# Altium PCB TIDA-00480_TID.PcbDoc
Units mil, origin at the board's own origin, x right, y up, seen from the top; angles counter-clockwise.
Board outline 5000 x 2500 mil, 2 copper layers (Layer 1 - Top Layer, Layer 2 - Bottom Layer), stack 93 mil thick; 63 components, 60 nets, 208 pads, 58 vias.
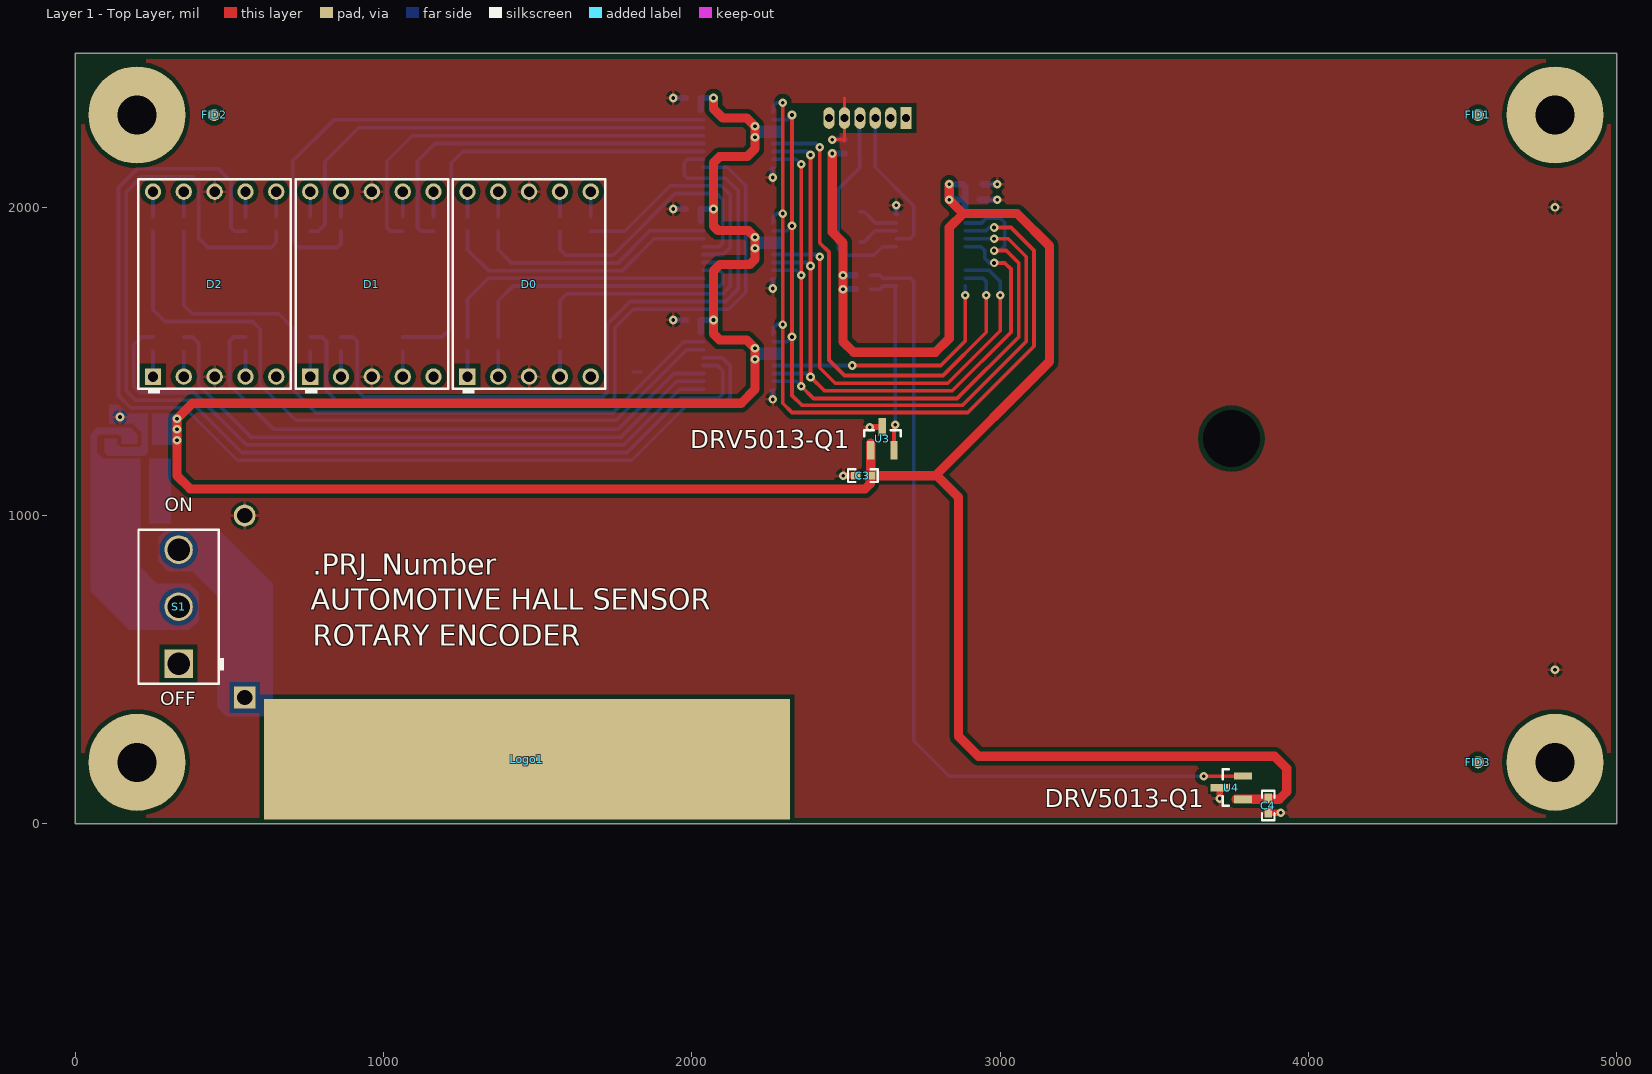
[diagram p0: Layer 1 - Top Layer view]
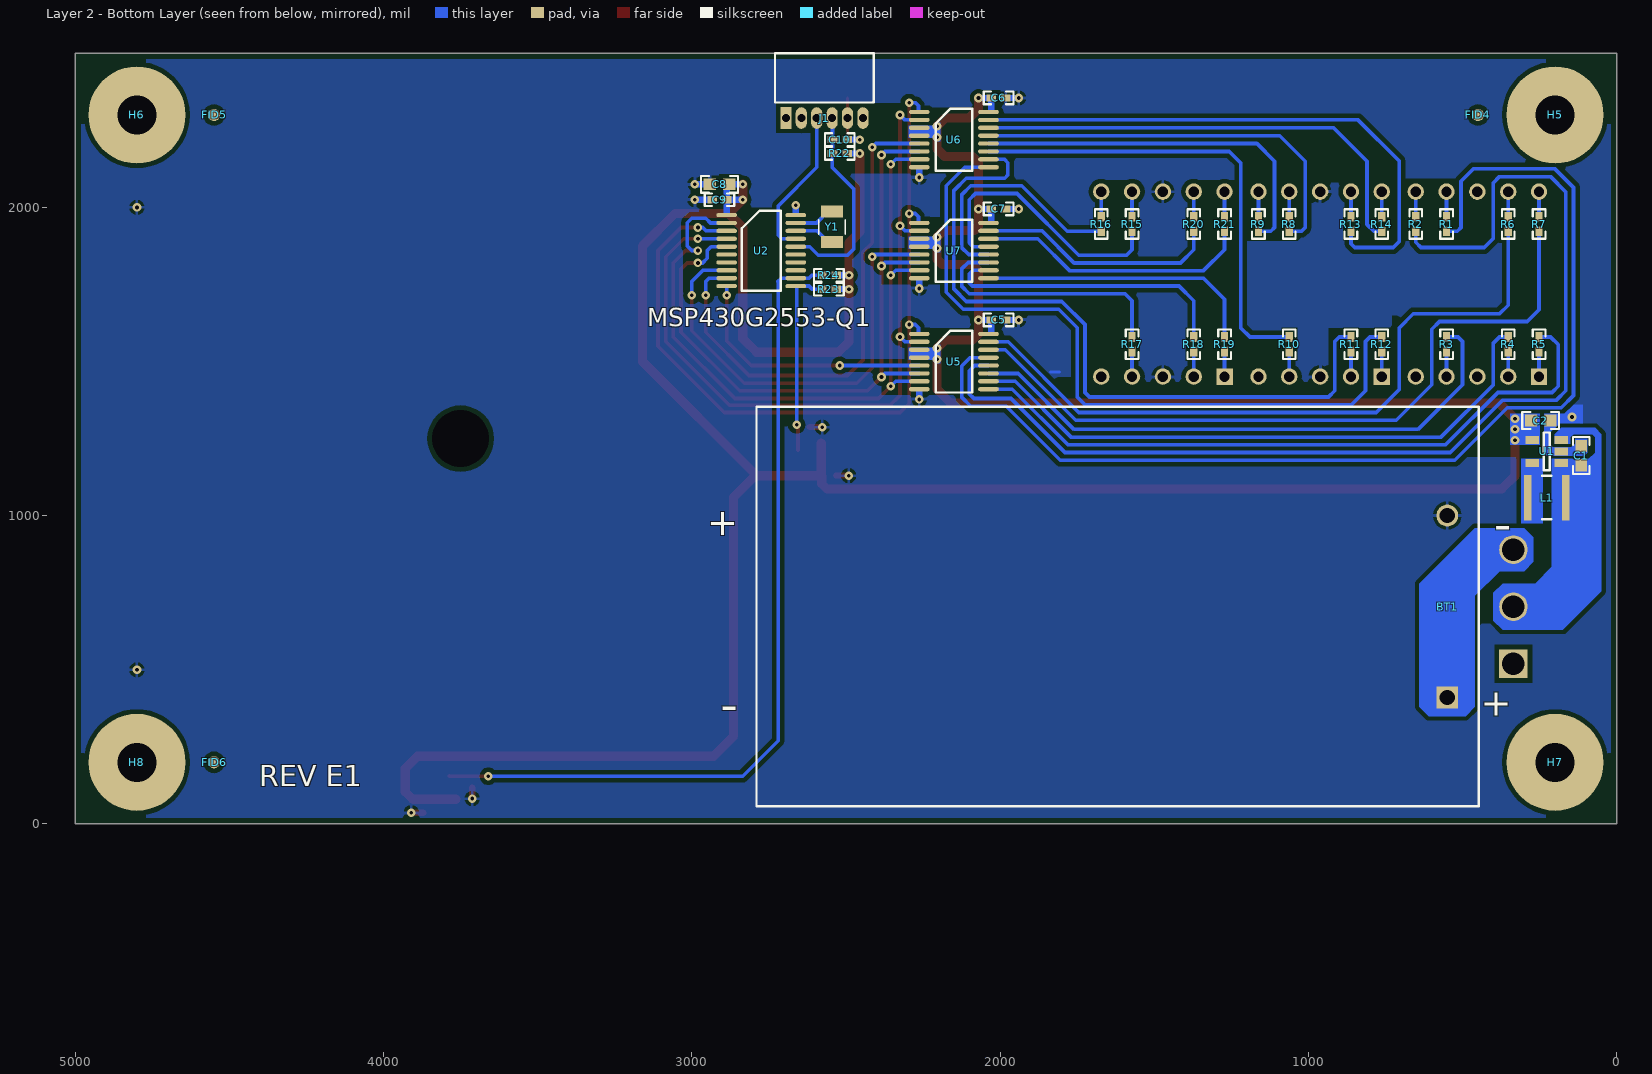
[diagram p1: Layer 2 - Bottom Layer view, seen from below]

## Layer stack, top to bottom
Top Solder: solder mask 0.4, Solder Resist, Dk 3.5
Layer 1 - Top Layer: signal copper 1.4
Dielectric1: core 90.2, 370HR, Dk 4.8
Layer 2 - Bottom Layer: signal copper 1.4
Bottom Solder: solder mask 0.4, Solder Resist, Dk 3.5

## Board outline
0,0 5000,0 5000,2500 0,2500

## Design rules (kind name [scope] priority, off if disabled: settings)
AcuteAngle [All] p1: minimum=4.50000000000000E+0001 checktracksonly=FALSE
AssemblyTestPointUsage [All] p1: valid=2
Clearance Clearance_BoardEdge_MountingHoles [OnCopper and InComponentClass('Mounting Holes') vs IsKeepOut] p1: gap=20
Clearance Clearance_BoardEdge_Poly [OnCopper and InPoly vs IsKeepOut] p2: gap=20
Clearance Clearance_BoardEdge [OnCopper and Not InComponentClass('Logo') and not InComponentClass('FiducialMark') and not InRegion(1000,500,4000,800) vs IsKeepOut] p3: gap=20
Clearance [All] p4: gap=8 except(15: Poly-Poly Poly-Text SMDPad-Poly Poly-Region Track-Poly Via-Poly Arc-Poly THPad-Poly Fill-Poly)
ComponentClearance ComponentClearance_Logo [InComponentClass(Logo)] p1 off: gap=50 collisioncheckmode=3 verticalgap=10 showdistances=FALSE
ComponentClearance ComponentClearance_ScrewToNut [(HasFootprint('NY PMS 440 0025 PH')) vs (HasFootprint('Keystone_1902C'))] p2 off: gap=5 collisioncheckmode=3 verticalgap=10 showdistances=FALSE
ComponentClearance ComponentClearance_MountingHoles [InComponentClass('Mounting Holes')] p3 off: gap=250 collisioncheckmode=3 verticalgap=100000 showdistances=FALSE
ComponentClearance ComponentClearance_SmallPassives [HasFootprint('0201*') or HasFootprint('0402*') or HasFootprint('0508') or HasFootprint('0603*') or HasFootprint('0612') or HasFootprint('0805*') or HasFootprint('0815*') or HasFootprint('0830*') or HasFootprint('1206*') or HasFootprint('1210*') or HasFootprint('1808*') or HasFootprint('1812*') or HasFootprint('1825*') or HasFootprint('2010*') or HasFootprint('2220*') or HasFootprint('2225*') or HasFootprint('2512*') or HasFootprint('2728*') or HasFootprint('3518*') vs HasFootprint('0201*') or HasFootprint('0402*') or HasFootprint('0508') or HasFootprint('0603*') or HasFootprint('0612') or HasFootprint('0805*') or HasFootprint('0815*') or HasFootprint('0830*') or HasFootprint('1206*') or HasFootprint('1210*') or HasFootprint('1808*') or HasFootprint('1812*') or HasFootprint('1825*') or HasFootprint('2010*') or HasFootprint('2220*') or HasFootprint('2225*') or HasFootprint('2512*') or HasFootprint('2728*') or HasFootprint('3518*')] p4 off: gap=20 collisioncheckmode=3 verticalgap=10 showdistances=FALSE
ComponentClearance ComponentClearance_THtoSMT [IsThruComponent vs IsSMTComponent] p5 off: gap=100 collisioncheckmode=3 verticalgap=100000 showdistances=FALSE
ComponentClearance ComponentClearance_THtoTH [IsThruComponent vs IsThruComponent] p6 off: gap=118.11 collisioncheckmode=3 verticalgap=100000 showdistances=FALSE
ComponentClearance [All] p7: gap=5 collisioncheckmode=3 verticalgap=10 showdistances=FALSE
DiffPairsRouting [All] p1: maxlimit=100 minlimit=10 mostfreqgap=10 toplayer_minwidth=15 toplayer_maxwidth=15 toplayer_prefwidth=15 bottomlayer_minwidth=15 bottomlayer_maxwidth=15 bottomlayer_prefwidth=15 maxuncoupledlength=1000
FabricationTestPointUsage TestPointUsage [All] p1: valid=2 allowmultiple=FALSE
FabricationTestpoint Testpoint [All] p1: side=3 testpointundercomponent=TRUE minsize=40 maxsize=100 preferedsize=60 minholesize=0 maxholesize=40 preferedholesize=32 testpointgrid=1 allowsidetop=TRUE allowsidebottom=TRUE usegrid=TRUE gridtolerance=0.01
FanoutControl Fanout_LCC [IsLCC] p1: bgadir=Out bgaviamode=Centered fanoutstyle=Auto fanoutdirection=Alternating viagrid=1 // Fanout_LCC (Default Rule)
FanoutControl Fanout_BGA [IsBGA] p2: bgadir=Out bgaviamode=Centered fanoutstyle=Auto fanoutdirection=Alternating viagrid=1 // Fanout_BGA (Default Rule)
FanoutControl Fanout_Default [All] p4: bgadir=Out bgaviamode=Centered fanoutstyle=Auto fanoutdirection=Alternating viagrid=1 // Fanout_Default (Default Rule)
FanoutControl Fanout_Small [(CompPinCount < 5)] p5: bgadir=Out bgaviamode=Centered fanoutstyle=Auto fanoutdirection=OutThenIn viagrid=1 // Fanout_Small (Default Rule)
Height [All] p1: minheight=0 maxheight=1500 prefheight=500
HoleSize [All] p1: absolutevalues=TRUE maxlimit=550 minlimit=5 maxpercent=80.000 minpercent=20.000
MinimumAnnularRing [All] p1: minimumring=5
MinimumSolderMaskSliver MinimumSolderMaskSliver_Logo [InComponentClass('Logo') vs InComponentClass('Logo')] p1: minsoldermaskwidth=0.7
MinimumSolderMaskSliver SilkscreenOverComponentPads [All] p2: minsoldermaskwidth=5
MinimumSolderMaskSliver [All] p3: minsoldermaskwidth=5
PlaneConnect [All] p1: planeconnectstyle=Relief reliefexpansion=10 reliefentries=4 reliefconductorwidth=10 reliefairgap=10
PolygonConnect [All] p1: connectstyle=Relief reliefconductorwidth=10 reliefentries=4 polygonreliefangle="90 Angle" airgapwidth=10
RoutingVias [All] p1: holewidth=12 width=28 viastyle="Through Hole" minholewidth=5 minwidth=20 maxholewidth=100 maxwidth=150
SMDToCorner [All] p1: distance=30000
SilkToSilkClearance [All] p1: silktosilkclearance=5
SilkToSolderMaskClearance [IsPad] p1: minsilkscreentomaskgap=5 clearancetoexposedcopper=TRUE
SolderMaskExpansion [All] p1: expansion=3
UnpouredPolygon [All] p1: allowunpoured=FALSE
Width [All] p1: maxlimit=100 minlimit=6 preferedwidth=10 checkconnectedcopper=TRUE
14 further rules are at their usual default settings.

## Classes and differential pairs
component class AssemblyNote: ZZ2 ZZ3 ZZ4
component class FiducialMark: FID1 FID2 FID3 FID4 FID5 FID6
component class TIDA-00480_TID_Hardware: FID1 FID2 FID3 FID4 FID5 FID6 H5 H6 H7 H8 Logo1 ZZ2 ZZ3 ZZ4
component class Logo: Logo1
component class TIDA-00480_TID_Schematic: BT1 C1 C2 C3 C4 C5 C6 C7 C8 C9 C10 D0 D1 D2 J1 L1 R1 R2 R3 R4 R5 R6 R7 R8 R9 R10 R11 R12 R13 R14 R15 R16 R17 R18 R19 R20 R21 R22 R23 R24 S1 U1 U2 U3 U4 U5 U6 U7 Y1

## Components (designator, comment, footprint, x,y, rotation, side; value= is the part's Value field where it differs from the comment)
BT1 "2462" Keystone_2462 1084.5,705.5 r0 bottom locked
C1 "GRM188R60J106ME47D" 0603 115,1195 r90 bottom
C2 "GRM188R60J106ME47D" 0603 246.66,1308.82 r180 bottom
C3 "GRM155R61A104KA01D" 0402 2555,1130 r180 top
C4 "GRM155R61A104KA01D" 0402 3870,60 r270 top
C5 "GRM155R61A104KA01D" 0402 2005,1635 r180 bottom
C6 "GRM155R61A104KA01D" 0402 2005,2355 r180 bottom
C7 "GRM155R61A104KA01D" 0402 2005,1995 r180 bottom
C8 "GRM188R60J106ME47D" 0603 2910.31,2075 r0 bottom
C9 "GRM155R61A104KA01D" 0402 2910.31,2025 r0 bottom
C10 "GRM155R60J102KA01D" 0402 2520,2220 r180 bottom
D0 "HDSP-H103" HDSP_M_N_Red 1472.04,1751.21 r0 top
D1 "HDSP-H103" HDSP_M_N_Red 962.04,1751.21 r0 top
D2 "HDSP-H103" HDSP_M_N_Red 452.04,1751.21 r0 top
FID1 "Fiducial" Fiducial10-20 4550,2300 r0 top
FID2 "Fiducial" Fiducial10-20 450,2300 r0 top
FID3 "Fiducial" Fiducial10-20 4550,200 r0 top
FID4 "Fiducial" Fiducial10-20 450,2300 r0 bottom
FID5 "Fiducial" Fiducial10-20 4550,2300 r0 bottom
FID6 "Fiducial" Fiducial10-20 4550,200 r0 bottom
H5 "2205" KEYSTONE_2205 200,2300 r180 bottom locked
H6 "2205" KEYSTONE_2205 4800,2300 r180 bottom locked
H7 "2205" KEYSTONE_2205 200,200 r180 bottom locked
H8 "2205" KEYSTONE_2205 4800,200 r180 bottom locked
J1 "851-43-006-20-001000" CONN_851-43-006-20-001000 2570,2290 r0 bottom
L1 "DO3314-103MLB" DO3314 226.66,1058.82 r0 bottom
Logo1 "Texas Instruments" TI_Horizontal_SolderMask_Medium 1465,210 r0 top
R1 "CRCW0402232RFKED" 0402 552.05,1946.22 r270 bottom
R2 "CRCW0402232RFKED" 0402 652.05,1946.22 r270 bottom
R3 "CRCW0402232RFKED" 0402 552.05,1556.22 r90 bottom
R4 "CRCW0402232RFKED" 0402 352.05,1556.22 r90 bottom
R5 "CRCW0402232RFKED" 0402 252.05,1556.22 r90 bottom
R6 "CRCW0402232RFKED" 0402 352.05,1946.22 r270 bottom
R7 "CRCW0402232RFKED" 0402 252.05,1946.22 r270 bottom
R8 "CRCW0402232RFKED" 0402 1062.05,1946.22 r270 bottom
R9 "CRCW0402232RFKED" 0402 1162.05,1946.22 r270 bottom
R10 "CRCW0402232RFKED" 0402 1062.05,1556.22 r90 bottom
R11 "CRCW0402232RFKED" 0402 862.05,1556.22 r90 bottom
R12 "CRCW0402232RFKED" 0402 762.05,1556.22 r90 bottom
R13 "CRCW0402232RFKED" 0402 862.05,1946.22 r270 bottom
R14 "CRCW0402232RFKED" 0402 762.05,1946.22 r270 bottom
R15 "CRCW0402232RFKED" 0402 1572.05,1946.22 r270 bottom
R16 "CRCW0402232RFKED" 0402 1672.05,1946.22 r270 bottom
R17 "CRCW0402232RFKED" 0402 1572.05,1556.22 r90 bottom
R18 "CRCW0402232RFKED" 0402 1372.05,1556.22 r90 bottom
R19 "CRCW0402232RFKED" 0402 1272.05,1556.22 r90 bottom
R20 "CRCW0402232RFKED" 0402 1372.05,1946.22 r270 bottom
R21 "CRCW0402232RFKED" 0402 1272.05,1946.22 r270 bottom
R22 "CRCW040247K0JNED" 0402 2520,2175 r180 bottom
R23 "CRCW04021K00JNED" 0402 2555.31,1735 r180 bottom
R24 "CRCW04021K00JNED" 0402 2555.31,1780 r180 bottom
S1 "500SSP1S2M2QEA" SW_500SSP1S2M2xxA 335,705 r90 top
U1 "TPS61097A-33DBVR" DBV0005A_N 226.66,1208.82 r0 bottom
U2 "MSP430G2553IPW0RQ1" PW0020A_N 2775,1860 r180 bottom
U3 "DRV5013ADQDBZRQ1" DBZ0003A_N 2618,1250 r90 top
U4 "DRV5013ADQDBZRQ1" DBZ0003A_N 3750,118 r180 top
U5 "CD4511BPWR" PW0016A_N 2150,1500 r180 bottom
U6 "CD4511BPWR" PW0016A_N 2150,2220 r180 bottom
U7 "CD4511BPWR" PW0016A_N 2150,1860 r180 bottom
Y1 "NX3215SA-32.768K-STD-MUS-2" XTAL_NX3215SA 2545.31,1937 r270 bottom
ZZ2 "These assemblies are ESD sensitive, ESD precautions shall be observed." AssemblyNote 185,3829.11 r0 top
ZZ3 "These assemblies must be clean and free from flux and all contaminants. Use of no clean flux is not acceptable." AssemblyNote 185,3740.56 r0 top
ZZ4 "These assemblies must comply with workmanship standards IPC-A-610 Class 2, unless otherwise specified." AssemblyNote 185,3652 r0 top

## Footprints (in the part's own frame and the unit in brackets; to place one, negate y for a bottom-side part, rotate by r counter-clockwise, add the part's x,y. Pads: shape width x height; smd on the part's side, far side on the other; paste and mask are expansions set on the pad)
0402 [mm] "0402 from SM-752 data"
  rect 0.8x0.6 smd: 1(-0.6,0) 2(0.6,0)
  silkscreen extent -1.22,-0.52 1.22,0.52, body extent -0.55,-0.3 0.55,0.3, height 0.6
0603 [mm] "0603 from SM-752 data"
  rect 1x0.95 smd: 1(-0.8,0) 2(0.8,0)
  silkscreen extent -1.52,-0.69 1.52,0.69, body extent -0.87,-0.47 0.87,0.47, height 0.85
AssemblyNote [mil] "Assembly Note"
CONN_851-43-006-20-001000 [mil] "Mill-Max"
  rect 36x70 hole 26: 1(125,0)
  oval 36x70 hole 26: 2(75,0) 3(25,0) 4(-25,0) 5(-75,0) 6(-125,0)
  silkscreen extent -160,-210 160,-50, body extent -158,-210 157,8, height 87
DBV0005A_N [mm] "SOT23, 5-Leads, Body 2.9x1.6mm, Pitch 0.95mm, Lead Span 2.8mm, IPC Medium Density"
  rect 1.1x0.65 smd: 1(-1.2,0.95) 2(-1.2,0) 3(-1.2,-0.95) 4(1.2,-0.95) 5(1.2,0.95)
  silkscreen extent -0.25,-1.55 0.25,1.55, body extent -1.42,-1.46 1.42,1.46, height 1.08
DBZ0003A_N [mm] "SOT23, 3-Leads, Body 2.9x1.3mm, Pitch 0.95mm, Lead Span 2.4mm, IPC Medium Density"
  rect 1.5x0.6 smd: 1(-0.95,0.95) 2(-0.95,-0.95) 3(0.95,0)
  silkscreen extent 0.2,-1.5 0.7,1.5, body extent -1.26,-1.46 1.26,1.46, height 0.96
DO3314 [mm] "COILCRAFT"
  rect 0.635x3.76 smd: 1(-1.564,0) 2(1.564,0)
  Layer 1 - Top Layer region: 1.354,-1.88 0.634,-1.88 0.634,-1.24 1.354,-1.24
  Layer 1 - Top Layer region: 1.684,1.24 0.634,1.24 0.634,1.88 1.684,1.88
  Layer 1 - Top Layer region: -1.566,1.88 -0.636,1.88 -0.636,1.24 -1.566,1.24
  Layer 1 - Top Layer region: -1.346,-1.24 -0.636,-1.24 -0.636,-1.88 -1.346,-1.88
  silkscreen extent -0.38,-1.8 0.38,1.8, body extent -1.75,-1.75 1.75,1.75, height 1.4
Fiducial10-20 [mm]
  round 1 smd mask+0.5: 1(0,0)
HDSP_M_N_Red [mm] "TH, 10-Leads, Body 12.573x17.02mm, Pitch 2.54mm"
  rect 1.35x1.35 hole 0.85: 1(-5.08,-7.62)
  round 1.35 hole 0.85: 2(-2.54,-7.62) 3(0,-7.62) 4(2.54,-7.62) 5(5.08,-7.62) 6(5.08,7.62) 7(2.54,7.62) 8(0,7.62) 9(-2.54,7.62) 10(-5.08,7.62)
  silkscreen extent -6.29,-9 6.29,8.63, body extent -6.29,-8.63 6.29,8.63, height 8.01
KEYSTONE_2205 [mil] "THREAD HEX ALUMINUM STANDOFF 4-40, F-F 1\""
  round 1 on Mech4: 0(0,0)
  body extent -148,-128 148,128, height 1001
Keystone_2462 [mm] "2x AA Battery Holder, Through-hole mount"
  rect 1.8x1.8 hole 1.27: 1(-13.59,7.495)
  round 1.8 hole 1.27: 2(-13.59,-7.495)
  silkscreen extent -16.18,-16.46 43.33,16.46, body extent -16.31,-16.46 43.4,16.46, height 16
PW0016A_N [mm] "TSOP, 16-Leads, Body 5x4.4mm, Pitch 0.65mm, IPC Medium Density"
  oval 1.7x0.35 smd: 1(-2.85,2.275) 2(-2.85,1.625) 3(-2.85,0.975) 4(-2.85,0.325) 5(-2.85,-0.325) 6(-2.85,-0.975) 7(-2.85,-1.625) 8(-2.85,-2.275) 9(2.85,-2.275) 10(2.85,-1.625) 11(2.85,-0.975) 12(2.85,-0.325) 13(2.85,0.325) 14(2.85,0.975) 15(2.85,1.625) 16(2.85,2.275)
  silkscreen extent -1.5,-2.55 1.5,2.55, body extent -3.21,-2.5 3.21,2.5, height 0.98
PW0020A_N [mm] "TSOP, 20-Leads, Body 6.5x4.4mm, Pitch 0.65mm, IPC Medium Density"
  oval 1.7x0.35 smd: 1(-2.85,2.925) 2(-2.85,2.275) 3(-2.85,1.625) 4(-2.85,0.975) 5(-2.85,0.325) 6(-2.85,-0.325) 7(-2.85,-0.975) 8(-2.85,-1.625) 9(-2.85,-2.275) 10(-2.85,-2.925) 11(2.85,-2.925) 12(2.85,-2.275) 13(2.85,-1.625) 14(2.85,-0.975) 15(2.85,-0.325) 16(2.85,0.325) 17(2.85,0.975) 18(2.85,1.625) 19(2.85,2.275) 20(2.85,2.925)
  silkscreen extent -1.6,-3.3 1.6,3.3, body extent -3.21,-3.25 3.21,3.25, height 0.99
SW_500SSP1S2M2xxA [mm] "TH, 3-Leads, Body 12.85x6.6mm, Pitch 4.7mm"
  rect 2.35x2.35 hole 1.85: 1(-4.7,0)
  round 2.35 hole 1.85: 2(0,0) 3(4.7,0)
  silkscreen extent -6.35,-3.75 6.35,3.3, body extent -6.35,-3.3 6.35,3.3, height 15.1
TI_Horizontal_SolderMask_Medium [mil]
  rect 1706x392 smd paste-200 mask-200: 0(0,0)
XTAL_NX3215SA [mm] "NDK recommended land pattern"
  rect 1x1.8 smd: 1(-1.25,0) 2(1.25,0)
  silkscreen extent -0.6,-1.1 0.6,1.1, body extent -1.65,-0.8 1.65,0.8, height 0.9

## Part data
BT1: "2x AA Battery Holder, Through-hole mount"
C1 C2 C8: "CAP, CERM, 10 µF, 6.3 V, +/- 20%, X5R, 0603"
C3 C4 C5 C6 C7 C9: "CAP, CERM, 0.1 µF, 10 V, +/- 10%, X5R, 0402"
C10: "CAP, CERM, 1000 pF, 6.3 V, +/- 10%, X5R, 0402"
D0 D1 D2: "LED, Red, TH"
FID1 FID2 FID3 FID4 FID5 FID6: "Fiducial mark.  There is nothing to buy or mount."
H5 H6 H7 H8: "Standoff, Hex, 1\"L #4-40 Aluminum"
J1: "Receptacle, 50mil, 6x1, Gold, R/A, TH"
L1: "Inductor, Drum Core, Ferrite, 10 µH, 0.75 A, 0.52 ohm, SMD"
Logo1: library part TI_Logo, "Texas Instrument Corporate Signature"
R1 R2 R3 R4 R5 R6 R7 R8 R9 R10 R11 R12 R13 R14 R15 R16 R17 R18 R19 R20 R21: "RES, 232, 1%, 0.063 W, 0402"
R22: "RES, 47 k, 5%, 0.063 W, 0402"
R23 R24: "RES, 1.0 k, 5%, 0.063 W, 0402"
S1: "Switch, SPDT, Slide, On-On, 2 Pos, TH"
U1: "Low-Input Voltage Synchronous-Boost Converter With Low Quiescent Current, DBV0005A"
U2: "Automotive Mixed-Signal Microcontrollers, PW0020A"
U3 U4: "Automotive Digital-Latch Hall Effect Sensor, DBZ0003A"
U5 U6 U7: "CMOS BCD-to-7-Segment LED Latch / Decoder / Driver, 3 to 18 V, -55 to 125 degC, 16-pin SOP (PW16), Green (RoHS & no Sb/Br)"
Y1: "Crystal, 32.768kHz, 12.5pF, SMD"
ZZ2 ZZ3 ZZ4: library part AssemblyNote

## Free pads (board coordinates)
  round 60 hole 185 unplated: 0(3750,1250)
  round 314.96 hole 125.98: ""(200,200) ""(200,2300) ""(4800,200) ""(4800,2300)

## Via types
v1: diameter 28, hole 12, Layer 1 - Top Layer to Layer 2 - Bottom Layer, tented both sides, 58 vias

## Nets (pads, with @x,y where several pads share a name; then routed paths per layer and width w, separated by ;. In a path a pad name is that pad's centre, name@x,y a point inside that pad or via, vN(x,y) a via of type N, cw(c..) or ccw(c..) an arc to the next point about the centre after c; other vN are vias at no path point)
3V3: C2.1 C3.1 C4.1 C5.1 C6.1 C7.1 C8.1 C9.1 R22.2 R23.2 R24.2 U1.4 U2.1 U3.1 U4.1 U5.3 U5.4 U5.16 U6.3 U6.4 U6.16 U7.3 U7.4 U7.16 | length 11760.1
  Layer 1 - Top Layer w20: C3.1 C3.1@2580.6,1131.98
  Layer 1 - Top Layer w30: v1(2070,2355) 2070,2320 2100,2290 2178,2290 v1(2205,2263) v1(2205,2228) 2205,2190 2180,2165 2090,2165 2070,2145 v1(2070,1995) 2070,1940 2085,1925 2183,1925 v1(2205,1903) v1(2205,1868) 2205,1831.82 2188.18,1815 2090.95,1815 2070,1794.05 v1(2070,1635) 2070,1590 2090,1570 2178,1570 v1(2205,1543) v1(2205,1508) 2205,1410 2160,1365 380,1365 v1(330,1315) v1(330,1280) v1(330,1245) 330,1130 373,1087 2562,1087 2578.62,1103.62 C3.1 ; v1(2455,2175) 2455,1920 2490.31,1884.69 v1(2490.31,1780) v1(2490.31,1735) 2490.31,1564.69 2525,1530 2790,1530 2835,1575 2835,1934.69 2880.31,1980 ; C3.1@2580.6,1130 2795,1130 2865,1060 2865,285 2930,220 3890,220 3930,180 3930,105 3905.6,80.6 U4.1 U4.1@3765,80.6 ; C3.1@2580.6,1131.98 U3.1 U3.1@2580.6,1235 ; 2792.5,1132.5 3160,1500 3160,1875 3055,1980 2880.31,1980 ; v1(2835.31,2075) v1(2835.31,2025) 2880.31,1980
  Layer 2 - Bottom Layer w20: U5.16@2028.62,1595 C5.1 v1(2070,1635) ; U7.16@2028.62,1955 C7.1 v1(2070,1995) ; U6.16@2028.62,2315 C6.1 v1(2070,2355) ; v1(2455,2175) R22.2 ; v1(2490.31,1735) R23.2 ; v1(2490.31,1780) R24.2 ; v1(2835.31,2025) C9.1 ; v1(2835.31,2075) C8.1 2886.69,2067.13 C9.1 ; U2.1@2886.69,1980 C9.1
GND: BT1.2 C1.2 C2.2 C3.2 C4.2 C5.2 C6.2 C7.2 C8.2 C9.2 C10.2 D0.3 D0.8 D1.3 D1.8 D2.3 D2.8 J1.5 U1.2 U2.20 U3.3 U4.3 U5.8 U6.8 U7.8 | length 747.5
  Layer 1 - Top Layer w10: v1(2455,2220) 2490,2220 2495,2215 J1.5 2495,2355
  Layer 1 - Top Layer w20: v1(2491.38,1130) C3.2 ; v1(2577.4,1287.4) U3.3 ; v1(3712.6,82.4) U4.3 ; C4.2 v1(3910,36.38)
  Layer 2 - Bottom Layer w10: 1808,1466 1836,1466
  Layer 2 - Bottom Layer w20: v1(1940,1635) C5.2 ; v1(1940,1995) C7.2 ; v1(1940,2355) C6.2 ; v1(2262.21,1377.2) U5.8@2262.21,1405 ; v1(2262.21,1737.2) U7.8@2262.21,1765 ; v1(2262.2,2097.2) U6.8@2262.2,2125 ; v1(2455,2220) C10.2 ; U2.20@2662.8,1980 v1(2662.8,2007.48) ; C9.2 v1(2990.31,2025) ; C8.2 v1(2990.31,2075)
  other v1: 4800,500 145,1320 4800,2000
NetBT1_1: BT1.1 S1.3
NetC1_1: C1.1 L1.1 S1.2 U1.1 U1.3
NetC10_1: C10.1 J1.4 R22.1 U2.16 | length 662.2
  Layer 2 - Bottom Layer w12: R22.1 C10.1 2543.62,2288.62 J1.4 ; R22.1@2545,2175 2545,2130 2475,2060 2475,1865 2495,1845 2590,1845 2617.8,1872.8 U2.16
NetD0_1: D0.1 R19.1 | length 81.4
  Layer 2 - Bottom Layer w12: D0.1 R19.1
NetD0_2: D0.2 R18.1 | length 81.4
  Layer 2 - Bottom Layer w12: D0.2 R18.1
NetD0_4: D0.4 R17.1 | length 81.4
  Layer 2 - Bottom Layer w12: D0.4 R17.1
NetD0_6: D0.6 R16.1 | length 81.4
  Layer 2 - Bottom Layer w12: R16.1 D0.6
NetD0_7: D0.7 R15.1 | length 81.4
  Layer 2 - Bottom Layer w12: R15.1 D0.7
NetD0_9: D0.9 R20.1 | length 81.4
  Layer 2 - Bottom Layer w12: R20.1 D0.9
NetD0_10: D0.10 R21.1 | length 81.4
  Layer 2 - Bottom Layer w12: R21.1 D0.10
NetD1_1: D1.1 R12.1 | length 81.4
  Layer 2 - Bottom Layer w12: D1.1 R12.1
NetD1_2: D1.2 R11.1 | length 81.4
  Layer 2 - Bottom Layer w12: D1.2 R11.1
NetD1_4: D1.4 R10.1 | length 81.4
  Layer 2 - Bottom Layer w12: D1.4 R10.1
NetD1_6: D1.6 R9.1 | length 81.4
  Layer 2 - Bottom Layer w12: R9.1 D1.6
NetD1_7: D1.7 R8.1 | length 81.4
  Layer 2 - Bottom Layer w12: R8.1 D1.7
NetD1_9: D1.9 R13.1 | length 81.4
  Layer 2 - Bottom Layer w12: R13.1 D1.9
NetD1_10: D1.10 R14.1 | length 81.4
  Layer 2 - Bottom Layer w12: R14.1 D1.10
NetD2_1: D2.1 R5.1 | length 81.4
  Layer 2 - Bottom Layer w12: D2.1 R5.1
NetD2_2: D2.2 R4.1 | length 81.4
  Layer 2 - Bottom Layer w12: D2.2 R4.1
NetD2_4: D2.4 R3.1 | length 81.4
  Layer 2 - Bottom Layer w12: D2.4 R3.1
NetD2_6: D2.6 R2.1 | length 81.4
  Layer 2 - Bottom Layer w12: R2.1 D2.6
NetD2_7: D2.7 R1.1 | length 81.4
  Layer 2 - Bottom Layer w12: R1.1 D2.7
NetD2_9: D2.9 R6.1 | length 81.4
  Layer 2 - Bottom Layer w12: R6.1 D2.9
NetD2_10: D2.10 R7.1 | length 81.4
  Layer 2 - Bottom Layer w12: R7.1 D2.10
NetJ1_3: J1.3 U2.17 | length 493.8
  Layer 2 - Bottom Layer w12: J1.3 2595,2130 2720,2005 2720,1910 2708.39,1898.39 U2.17
NetL1_2: L1.2 U1.5
NetR1_2: R1.2 U5.13 | length 3639.2
  Layer 2 - Bottom Layer w12: R1.2 517.4,1922.6 505,1935 505,2085 465,2125 200,2125 140,2065 140,1390 180,1350 355,1350 525,1180 1805,1180 1980,1355 2095,1355 2125,1385 2125,1485 2097.2,1512.8 U5.13
NetR2_2: R2.2 U5.12 | length 3637
  Layer 2 - Bottom Layer w12: R2.2 652.05,1887.05 635,1870 430,1870 400,1900 400,2080 380,2100 215,2100 165,2050 165,1405 195,1375 370,1375 540,1205 1790,1205 1965,1380 2085,1380 2100,1395 2100,1470 2082.8,1487.2 U5.12
NetR3_2: R3.2 U5.11 | length 1871.3
  Layer 2 - Bottom Layer w12: R3.2 514.84,1579.84 500,1565 500,1425 645,1280 1760,1280 1941.61,1461.61 U5.11
NetR4_2: R4.2 U5.10 | length 1974.4
  Layer 2 - Bottom Layer w12: R4.2 380.16,1579.84 400,1560 400,1425 570,1255 1770,1255 1951.02,1436.02 U5.10
NetR5_2: R5.2 U5.9 | length 2208.6
  Layer 2 - Bottom Layer w12: R5.2 214.84,1579.84 190,1555 190,1420 210,1400 385,1400 555,1230 1780,1230 1960.43,1410.43 U5.9
NetR6_2: R6.2 U5.15 | length 2281.5
  Layer 2 - Bottom Layer w12: R6.2 352.05,1682.95 380,1655 660,1655 705,1610 705,1410 780,1335 1745,1335 1973.98,1563.98 U5.15
NetR7_2: R7.2 U5.14 | length 2388.7
  Layer 2 - Bottom Layer w12: R7.2 252.05,1667.95 290,1630 575,1630 600,1605 600,1425 715,1310 1755,1310 1983.39,1538.39 U5.14
NetR8_2: R8.2 U6.13 | length 1334.3
  Layer 2 - Bottom Layer w12: R8.2 1022.4,1922.6 1010,1935 1010,2150 1092.8,2232.8 U6.13
NetR9_2: R9.2 U6.12 | length 1223.7
  Layer 2 - Bottom Layer w12: R9.2 1122.4,1922.6 1110,1935 1110,2150 1167.2,2207.2 U6.12
NetR10_2: R10.2 U6.11 | length 1538.4
  Layer 2 - Bottom Layer w12: R10.2 1189.84,1579.84 1220,1610 1220,2145 1256.61,2181.61 U6.11
NetR11_2: R11.2 U6.10 | length 2359.3
  Layer 2 - Bottom Layer w12: R11.2 900.16,1579.84 915,1565 915,1405 935,1385 1710,1385 1725,1400 1725,1620 1800,1695 2110,1695 2150,1735 2150,2055 2110,2095 1985,2095 1975,2105 1975,2145 1986.02,2156.02 U6.10
NetR12_2: R12.2 U6.9 | length 2388
  Layer 2 - Bottom Layer w12: R12.2 800.16,1579.84 815,1565 815,1405 860,1360 1725,1360 1750,1385 1750,1610 1810,1670 2120,1670 2175,1725 2175,2070 2114.57,2130.43 U6.9
NetR13_2: R13.2 U6.15 | length 1859.2
  Layer 2 - Bottom Layer w12: R13.2 862.05,1882.05 850,1870 725,1870 705,1890 705,2150 838.98,2283.98 U6.15
NetR14_2: R14.2 U6.14 | length 1534.9
  Layer 2 - Bottom Layer w12: R14.2 787.6,1922.6 810,1945 810,2150 918.39,2258.39 U6.14
NetR15_2: R15.2 U7.13 | length 893.4
  Layer 2 - Bottom Layer w12: R15.2 1572.05,1862.95 1590,1845 1745,1845 1945,2045 2080,2045 2100,2025 2100,1885 2087.79,1872.79 U7.13
NetR16_2: R16.2 U7.12 | length 793.1
  Layer 2 - Bottom Layer w12: R16.2 1782.6,1922.6 1930,2070 2095,2070 2125,2040 2125,1870 2102.2,1847.2 U7.12
NetR17_2: R17.2 U7.11 | length 841.2
  Layer 2 - Bottom Layer w12: R17.2 1572.05,1697.05 1595,1720 2100,1720 2125,1745 2125,1800 2103.39,1821.61 U7.11
NetR18_2: R18.2 U7.10 | length 965.9
  Layer 2 - Bottom Layer w12: R18.2 1372.05,1697.05 1420,1745 2090,1745 2100,1755 2100,1785 2088.98,1796.02 U7.10
NetR19_2: R19.2 U7.9 | length 916.3
  Layer 2 - Bottom Layer w12: R19.2 1272.05,1702.05 1340.43,1770.43 U7.9
NetR20_2: R20.2 U7.15 | length 786.3
  Layer 2 - Bottom Layer w12: R20.2 1372.05,1862.95 1415,1820 1760,1820 1863.97,1923.97 U7.15
NetR21_2: R21.2 U7.14 | length 896.4
  Layer 2 - Bottom Layer w12: R21.2 1272.05,1862.95 1340,1795 1775,1795 1878.38,1898.38 U7.14
NetR23_1: R23.1 U2.11 U3.2 | length 623.1
  Layer 1 - Top Layer w12: U3.2 2655.4,1290.4 v1(2660,1295)
  Layer 2 - Bottom Layer w12: R23.1 2610.31,1735 2620.16,1744.84 U2.11 ; v1(2660,1295) 2660,1742.36 U2.11@2662.48,1744.84
NetR24_1: R24.1 U2.12 U4.2 | length 2754.9
  Layer 1 - Top Layer w12: v1(3660,155) 3787,155 U4.2
  Layer 2 - Bottom Layer w12: R24.1 2610.31,1780 2619.88,1770.43 U2.12 2709.88,1770.43 2720.31,1760 ; 2720,1760 2720,270 2835,155 v1(3660,155)
NetU2_2: U2.2 U5.7 U6.7 U7.7 | length 2415.9
  Layer 1 - Top Layer w12: v1(2355,2140) v1(2355,1780) v1(2355,1420) 2395,1380 2860,1380 3060,1580 3060,1820 3020,1860 v1(2980.31,1860)
  Layer 2 - Bottom Layer w12: U5.7 2338.98,1436.02 v1(2355,1420) ; U7.7 2338.98,1796.02 v1(2355,1780) ; U6.7 2338.98,2156.02 v1(2355,2140) ; U2.2 2939.88,1949.57 2955.31,1965 3000.31,1965 3015.31,1950 3015.31,1875 3000.31,1860 v1(2980.31,1860)
NetU2_3: U2.3 U5.1 U6.1 U7.1 | length 2627.1
  Layer 1 - Top Layer w12: v1(2295,2340) v1(2295,1980) v1(2295,1620) 2295,1365 2325,1335 2895,1335 3110,1550 3110,1860 3035,1935 v1(2980.31,1935)
  Layer 2 - Bottom Layer w12: U5.1 2265,1592.36 2265,1610 2275,1620 v1(2295,1620) ; U7.1 2265,1952.36 2265,1970 2275,1980 v1(2295,1980) ; U6.1 2265,2312.36 2265,2330 2275,2340 v1(2295,2340) ; U2.3 2953.98,1923.98 2965,1935 v1(2980.31,1935)
NetU2_4: U2.4 U5.2 U6.2 U7.2 | length 2474.3
  Layer 1 - Top Layer w12: v1(2325,2300) v1(2325,1940) v1(2325,1580) 2325,1390 2357,1358 2878,1358 3085,1565 3085,1840 3026.61,1898.39 v1(2980.31,1898.39)
  Layer 2 - Bottom Layer w12: U5.2 2308.98,1563.98 v1(2325,1580) ; U7.2 2308.98,1923.97 v1(2325,1940) ; U6.2 2308.98,2283.98 v1(2325,2300) ; U2.4 v1(2980.31,1898.39)
NetU2_5: U2.5 U5.6 U6.6 U7.6 | length 2247.8
  Layer 1 - Top Layer w12: v1(2385,2170) v1(2385,1810) v1(2385,1450) 2430,1405 2845,1405 3035,1595 3035,1800 3015,1820 v1(2980.31,1820)
  Layer 2 - Bottom Layer w12: U5.6 2373.39,1461.61 v1(2385,1450) ; U7.6 2373.39,1821.61 v1(2385,1810) ; U6.6 2373.39,2181.61 v1(2385,2170) ; U2.5 2937.52,1872.8 2950.31,1860 2950.31,1835 2965.31,1820 v1(2980.31,1820)
NetU2_8: U2.8 U7.5 | length 1479.6
  Layer 1 - Top Layer w12: v1(2415,1840) 2415,1480 2465,1430 2830,1430 3000,1600 v1(3000,1715)
  Layer 2 - Bottom Layer w12: U7.5 2407.8,1847.2 v1(2415,1840) ; U2.8 2963.98,1796.02 3000,1760 v1(3000,1715)
NetU2_9: U2.9 U6.5 | length 1686.1
  Layer 1 - Top Layer w12: v1(2415,2195) 2415,1885 2445,1855 2445,1505 2495,1455 2815,1455 2955,1595 v1(2955,1715)
  Layer 2 - Bottom Layer w12: U6.5 2402.8,2207.2 v1(2415,2195) ; U2.9 2944.57,1770.43 2955,1760 v1(2955,1715)
NetU2_10: U2.10 U5.5 | length 838
  Layer 1 - Top Layer w12: v1(2520,1487.2) 2807.2,1487.2 2887.2,1567.2 v1(2887.2,1715)
  Layer 2 - Bottom Layer w12: U5.5 v1(2520,1487.2) ; v1@2887.2,1712.8 v1(2887.2,1715) U2.10
NetU2_18: U2.18 Y1.2 | length 132.5
  Layer 2 - Bottom Layer w12: Y1.2 2558.1,1887.79 2594.29,1923.98 U2.18
NetU2_19: U2.19 Y1.1 | length 132.7
  Layer 2 - Bottom Layer w12: Y1.1 2559.1,1986.21 2595.75,1949.57 U2.19
pads on no net: D0.5 D1.5 D2.5 FID1.1 FID2.1 FID3.1 FID4.1 FID5.1 FID6.1 H5.0 H6.0 H7.0 H8.0 J1.1 J1.2 J1.6 Logo1.0 S1.1 U2.6 U2.7 U2.13 U2.14 U2.15

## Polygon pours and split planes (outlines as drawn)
GND on Layer 1 - Top Layer "Layer 1 - Top Layer-GND" (solid, remove dead copper, pour order 4): 20,20 4980,20 4980,2480 20,2480
GND on Layer 2 - Bottom Layer "Layer 2 - Bottom Layer-GND" (solid, remove dead copper, pour order 3): 20,20 4980,20 4980,2480 20,2480

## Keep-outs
Keep-Out Layer:
  text ".Layer_Name" at 577,-858.49 h60

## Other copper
Layer 1 - Top Layer:
  pour cut-out: 2320,2170 2320,2340 2730,2340 2730,2240 2480,2240 2480,2170 2440,2170
  text ".Layer_Name" at 577,-858.49 h60
Layer 2 - Bottom Layer:
  region net GND: 135,1250 135,1234 147,1222 207,1222 215,1230 215,1270 195,1290 195,1330 235,1330 235,1205 225,1195 105,1195 95,1205 95,1250
  region net NetBT1_1: 300,820 270,850 270,930 300,960 460,960 640,780 640,380 610,350 490,350 460,380 460,740 380,820
  region net NetL1_2: 240,1185 310,1185 310,975 240,975
  region net NetC1_1: 400,660 370,630 175,630 50,755 50,1265 70,1285 180,1285 201,1264 201,1233 150,1233 150,1255 140,1265 80,1265 70,1255 70,1205 90,1185 210,1185 210,835 265,780 370,780 400,750
  region net 3V3: 2296,1866 2221,1866 2210,1855 2195,1855 2195,1915 2211,1915 2221,1905 2296,1905
  region net 3V3: 2296,2226 2221,2226 2210,2215 2195,2215 2195,2275 2211,2275 2221,2265 2296,2265
  region net 3V3: 2296,1506 2221,1506 2210,1495 2195,1495 2195,1555 2211,1555 2221,1545 2296,1545
  region net 3V3: 250,1230 345,1230 345,1310 345,1330 325,1330 250,1330
  pour cut-out: 415,1890 415,2095 685,2095 685,1890
  pour cut-out: 510,1425 380,1425 380,1610 510,1610
  pour cut-out: 730,1650 730,1610 935,1610 935,1570 710,1570 710,1650
  pour cut-out: 1200,1890 1035,1890 1023,1902 1020,1902 1020,1905 1200,1905
  pour cut-out: 825,2080 1060,2080 1060,2240 825,2240
  pour cut-out: 1380,1810 1380,2090 1240,2090 1240,1810
  pour cut-out: 1765,1905 1660,1905 1660,2090 1585,2090 1585,1865 1765,1865
  pour cut-out: 2090.95,2110 2230,2110 2230,2325 2095.55,2325 2090.95,2320.39
  pour cut-out: 2090,1750 2240,1750 2240,1970 2090,1970
  pour cut-out: 2090,1390 2230,1390 2230,1610 2090,1610
  pour cut-out: 2710,1720 2860,1720 2860,2000 2710,2000
  pour cut-out: 2665,1965 2490,1965 2490,2070 2545,2125 2585,2125 2665,2045
  pour cut-out: 2480,1830 2615,1830 2615,1795 2480,1795
  pour cut-out: 410,650 455,650 455,755 410,755
  pour cut-out: 240,1190 240,1230 355,1230 355,1310 370,1310 490,1190
  region net GND: 205,1300 205,1280 185,1300 110,1300 110,1330 110,1360 140,1360 170,1330 205,1330
  pour cut-out: 1395,1405 1395,1435 1555,1435 1555,1405
  pour cut-out: 2305,2225 2615,2225 2615,2240 2725,2240 2725,2340 2305,2340
  pour cut-out: 1765,1395 1815,1395 1815,1450 1765,1450
  pour cut-out: 1875,1945 2000,1945 2000,1985 1875,1985
  pour cut-out: 2285,2110 2525,2110 2525,2160 2285,2160
  pour cut-out: 2285,1750 2385,1750 2385,1785 2285,1785
  pour cut-out: 2285,1390 2385,1390 2385,1420 2285,1420
  pour cut-out: 2925,1980 2975,1980 2975,2010 2925,2010
  pour cut-out: 3000,1730 3030,1730 3030,1865 3000,1865
  pour cut-out: 975,1405 975,1435 1045,1435 1045,1405
  text ".Layer_Name" at 577,-858.49 h60

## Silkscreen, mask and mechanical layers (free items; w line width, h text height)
Top Overlay:
  text "DRV5013-Q1" at 1995,1200 h100
  text "ON" at 290,1000 h75
  text ".PRJ_Number" at 770,785 h115
  text "AUTOMOTIVE HALL SENSOR" at 763.5,671.5 h115
  text "ROTARY ENCODER" at 770,555 h115
  text "OFF" at 275,370 h75
  text "DRV5013-Q1" at 3145,35 h100
  text ".Layer_Name" at 577,-858.49 h60
Bottom Overlay:
  text "MSP430G2553-Q1" at 3145,1595 h100
  text "REV E1" at 4403,100 h115
  text ".Layer_Name" at 577,-858.49 h60
Top Paste:
  text ".Layer_Name" at 577,-858.49 h60
Bottom Paste:
  text ".Layer_Name" at 577,-858.49 h60
Top Solder:
  text ".Layer_Name" at 577,-858.49 h60
  text ".Layer_Name" at 577,-858.49 h60
Bottom Solder:
  text ".Layer_Name" at 577,-858.49 h60
Drill Guide:
  text ".Layer_Name" at 577,-858.49 h60
M1 Board Outline:
  the board outline again, w10
  text ".Layer_Name" at 577,-858.49 h60
M2 Board Dimensions:
  rectangle: 125,-400 500,-275
  rectangle: 0,-275 125,-150
  lines w7: 0,-275 1000,-275 ; 125,-400 125,-150 ; 250,-400 250,-150 ; 500,-400 500,-150 ; 750,-400 750,-150 ; 0,-400 0,-150 1000,-150 1000,-400 0,-400
  text ".Layer_Name" at 577,-858.49 h60
M3 3D STEP Top:
  text ".Layer_Name" at 577,-858.49 h60
M4 3D STEP Bottom:
  text ".Layer_Name" at 577,-858.49 h60
M5 Assembly Top:
  circle w5: c3750,1250 r935
  circle w5: c3750,1250 r1132
  lines w10: -292,-930.17 6308,-930.17 ; -292,-726.83 6310,-726.83 ; -292,-523.5 -292,-1133.5 3713,-1133.5 6310,-1133.5 6310,-523.5 -291.5,-523.5 -291.5,-1133.5 1284,-1133.5 ; 2173,-1133.5 2173,-523.5 ; 3440,-726.83 3440,-523.5 ; 4280,-726.83 4280,-523.5 ; 4902,-1140 4902,-937.17
  text "COMPONENTS MARKED 'DNP' SHOULD NOT BE POPULATED." at 1153.5,-318.5 h60
  text "ASSEMBLY VARIANT:" at 1153,-434 h60
  text ".VariantName" at 2189,-434 h60
  text "PCB VIEWED FROM TOP SIDE" at -228.5,-655.67 h60
  text "BOARD #:" at 2248,-655.67 h60
  text ".PRJ_Number" at 2793.5,-655.67 h60
  text "REV:" at 3638,-655.67 h60
  text ".PCB_Rev" at 3929.5,-655.67 h60
  text "SVN REV:" at 4476,-655.67 h60
  text ".VersionControl_RevNumber" at 4982,-655.67 h60
  text "PLOT NAME =" at -228.5,-1064.34 h60
  text ".plot_File_Name" at 577,-1064.34 h60
  text "GENERATED    :" at 2250,-1064.34 h60
  text ".Print_Date" at 3119.5,-1064.34 h60
  text ".Print_Time" at 3848.5,-1064.34 h60
  text "TEXAS INSTRUMENTS" at 5113,-1064.34 h60
M6 Assembly Bottom:
  lines w10: -292.5,-727.33 6309.5,-727.33 ; -290.5,-930.67 6309.5,-930.67 ; 1115.5,-1140.5 1115.5,-937.67 ; 1737.5,-727.33 1737.5,-524 ; 2577.5,-727.33 2577.5,-524 ; 3844.5,-1134 3844.5,-524 ; 4733.5,-1134 6309,-1134 6309,-524 -292.5,-524 -292.5,-1134 2304.5,-1134 6309.5,-1134 6309.5,-524
  text "COMPONENTS MARKED 'DNP' SHOULD NOT BE POPULATED." at 6102,-318 h60
  text ".VariantName" at 5058,-434 h60
  text "ASSEMBLY VARIANT:" at 6097,-434 h60
  text ".VersionControl_RevNumber" at 1035.5,-656.17 h60
  text "SVN REV:" at 1541.5,-656.17 h60
  text ".PCB_Rev" at 2088,-656.17 h60
  text "REV:" at 2379.5,-656.17 h60
  text ".PRJ_Number" at 3224,-656.17 h60
  text "BOARD #:" at 3769.5,-656.17 h60
  text "PCB VIEWED FROM BOTTOM SIDE" at 6246,-656.17 h60
  text "TEXAS INSTRUMENTS" at 904.5,-1064.84 h60
  text ".Print_Time" at 2169,-1064.84 h60
  text ".Print_Date" at 2898,-1064.84 h60
  text "GENERATED    :" at 3767.5,-1064.84 h60
  text ".plot_File_Name" at 5440.5,-1064.84 h60
  text "PLOT NAME =" at 6246,-1064.84 h60
M9 Title Sheet:
  drawing of 1178 lines, arcs and shapes, not listed
  text "1" at 739.84,8036.5 h70
  text "2" at 3235.5,8036.5 h70
  text "3" at 5724.84,8036.5 h70
  text "4" at 8231.51,8036.5 h70
  text "5" at 10730.5,8036.5 h70
  text "6" at 13235.5,8036.5 h70
  text "A" at -416.5,6893.5 h70
  text "A" at 14383.5,6893.5 h70
  text "B" at -416.5,4513.5 h70
  text "B" at 14383.5,4513.5 h70
  text "C" at -416.5,2138.5 h70
  text "C" at 14383.5,2138.5 h70
  text "PROJECT TITLE:" at 11343.5,277.5 h45
  text ".PRJ_Title" at 11393.5,144.17 h70
  text "DESIGNED FOR:" at 11343.5,-23.5 h45
  text ".PRJ_Customer" at 11393.5,-163.5 h70
  text "D" at -416.5,-231.5 h70
  text "D" at 14383.5,-231.5 h70
  text "FILE NAME:" at 11343.5,-323.5 h45
  text ".PCB_File_Name_No_Path" at 11393.5,-443.5 h70
  text "Texas Instruments (TI) and/or its licensors do not warrant the accuracy or completeness of this specification" at 6374,-605.34 h45
  text "ENGINEER:" at 11343.5,-613.5 h45
  text "LAYOUT BY:" at 12848.5,-613.5 h45
  text "or any information contained therein. TI and/or its licensors do not warrant that this design will meet" at 6329.01,-718 h45
  text ".PRJ_Engineer" at 11393.5,-768.49 h70
  text ".PCB_Layout" at 12899,-768.49 h70
  text "JMM" at 12838,-798 h75
  text "s  o  l  u  t  i  o  n  s" at 13712,-803 h68
  text "the specifications, will be suitable for your application or fit for any particular purpose, or will operate in" at 6329.01,-830.67 h45
  text ".Layer_Name" at 577,-858.49 h60
  text "ALTIUM DESIGNER VERSION:" at 12848.5,-923.5 h45
  text "an implementation. TI and/or its licensors do not warrant that the design is production worthy. You should" at 6329.01,-943.33 h45
  text "completely validate and test your design implementation to confirm the system functionality for your application." at 6374,-1056 h45
  text ".print_Scale" at 11393.5,-1056.83 h70
  text ".Application_BuildNumber" at 12899,-1056.83 h70
  text "1" at 739.84,-1263.5 h70
  text "2" at 3235.5,-1263.5 h70
  text "3" at 5724.84,-1263.5 h70
  text "4" at 8231.51,-1263.5 h70
  text "5" at 10730.5,-1263.5 h70
  text "6" at 13235.5,-1263.5 h70
M10 Fab Notes:
  drawing of 185 lines, arcs and shapes, not listed
  text "DESIGN INFORMATION" at 12381.02,5910 h60
  text "MIN. TRACK WIDTH:" at 11736.46,5730 h60
  text "12" at 12805,5730 h60
  text "MIL" at 12987.46,5730 h60
  text "MIN. CLEARANCE:" at 11736.46,5598 h60
  text "0.2" at 12772.7,5598 h60
  text "mm" at 12987.46,5598 h60
  text "MIN. VIA PAD SIZE:" at 11736.46,5466 h60
  text "28" at 12802.71,5466 h60
  text "MIL" at 12987.46,5466 h60
  text "0.05mm (2MIL)" at 12431.46,5324.29 h60
  text "MINIMUM ANNULAR RING" at 11407.23,5320 h60
  text "EXTERNAL" at 13139.46,5320 h60
  text "PER" at 11607.23,5202 h60
  text "IPC-D-275 CLASS 2 LEVEL C" at 11827.23,5202 h60
  text "MIL, HOLES" at 13315.46,5089.71 h60
  text "+/-" at 12923,5089 h60
  text "+/-" at 13777,5089 h60
  text "REGISTRATION TOLERANCES:" at 11407.23,5084 h60
  text "METAL" at 12607,5084 h60
  text "5" at 13183.2,5084 h60
  text "3" at 14016.2,5084 h60
  text "MIL" at 14132.46,5084 h60
  text "MATERIAL:" at 11332.46,4874.54 h60
  text "FR-4 High Tg" at 12318.9,4734.21 h60
  text "FR-408" at 11753.46,4725.64 h60
  text "X" at 12165.46,4725.64 h60
  text "OTHER" at 13241.46,4725.64 h60
  text "62 MIL (1.6mm) +/-10%" at 12073.56,4562.92 h60
  text "X" at 13200,4560 h60
  text "93 MIL +/-10%" at 13620,4560 h60
  text "THICKNESS:" at 11407.23,4558.64 h60
  text "OTHER" at 13323.46,4558.64 h60
  text "TOLERANCE:" at 11407.23,4400.64 h60
  text "X" at 12246.53,4400.64 h60
  text "ANSI IPC-6012 TYPE 3 CLASS 2" at 12433.48,4400.64 h60
  text "OTHER +/-" at 12433.46,4244.64 h60
  text "BOW & TWIST:" at 11407.23,4087.64 h60
  text "X" at 12246.53,4087.64 h60
  text "ANSI IPC-6012 TYPE 3 CLASS 2" at 12433.48,4087.64 h60
  text "OTHER +/-" at 12433.46,3929.13 h60
  text "DRILLING:" at 11332.46,3790.64 h60
  text "REFERENCE:" at 11407.23,3673.64 h60
  text "X" at 12055.46,3673.64 h60
  text "AS SHOWN" at 12242.46,3673.64 h60
  text "X" at 12956.46,3673.64 h60
  text "NC_DRILL FILES" at 13093.46,3673.64 h60
  text "PTH MIN COPPER THICKNESS:" at 11407.23,3515.64 h60
  text "X" at 12757.46,3515.64 h60
  text "1MIL" at 12894.46,3515.64 h60
  text "OTHER" at 13391.46,3515.64 h60
  text "BOARD FINISH:" at 11332.46,3356.64 h60
  text "SILKSCREEN:" at 11487.68,3238.64 h60
  text "X" at 12436.46,3238.64 h60
  text "TOP" at 12562.46,3238.64 h60
  text "X" at 12946.46,3238.64 h60
  text "BOTTOM" at 13073.46,3238.64 h60
  text "SILKSCREEN COLOR:" at 11487.68,3071.64 h60
  text "WHITE" at 12562.46,3071.64 h60
  text "OTHER" at 13073.46,3071.64 h60
  text "X" at 12435,3070 h60
  text "SOLDER RESIST COLOR:" at 11487.68,2901.64 h60
  text "Fab. shop may not add any markings to the top" at 8175,2750 h125
  text "GREEN" at 12182.46,2742.44 h60
  text "BLUE" at 12773.46,2742.44 h60
  text "X" at 13155.42,2742.44 h60
  text "OTHER" at 13311.46,2742.44 h60
  text "BLACK" at 13761.46,2742.44 h60
  text "of the board. U/L and RoHS may be added to the bottom." at 8175,2625 h125
  text "IMMERSION GOLD (ENIG)" at 12393.46,2553.92 h60
  text "ENEPIG" at 13731,2550.64 h60
  text "SURFACE FINISH:" at 11332.46,2549.64 h60
  text "X" at 12206.51,2549.64 h60
  text "All vias must be tented on top and bottom." at 8175,2495 h125
  text "IMM. TIN/SILVER OR EQUIV" at 11662,2392.64 h60
  text "OTHER" at 13093.46,2392.64 h60
  text "Soldermask must have glossy finish." at 8175,2370 h125
  text "ARRAY/PANEL:" at 11332.46,2213.64 h60
  text "CUT AND TRIM PER MECH LAYER 1" at 12393.46,2209.35 h60
  text "N.C. ROUTE" at 12393.46,2057.64 h60
  text "X" at 13072.46,2057.64 h60
  text "V. SCORE" at 13259.46,2057.64 h60
  text "CERTIFICATION:" at 11332.46,1920.64 h60
  text "MATERIALS AND WORKMANSHIP FOR ALL PCBS" at 12057.46,1920.64 h60
  text "TO MEET OR EXCEED THE REQUIREMENTS OF:" at 12057.46,1822.64 h60
  text "X" at 11683.96,1686.13 h60
  text "ANSI IPC-A-600F CLASS ->" at 11822.96,1686.13 h60
  text "X" at 13462.02,1686.13 h60
  text "2" at 13580.96,1686.14 h60
  text "1" at 13265.96,1684.64 h60
  text "3" at 13934.96,1684.64 h60
  text "X" at 11686.02,1526.64 h60
  text "UL 94V-0" at 11822.96,1526.64 h60
  text "X" at 12498.02,1526.64 h60
  text "RoHS" at 12634.96,1526.64 h60
  text "OTHER" at 13279.36,1526.64 h60
  text "PER ORDER" at 13676.42,1526.64 h60
  text "ADDITIONAL REQUIREMENTS:" at 11332.46,1385.64 h60
  text "MICROSECTION:" at 11407.23,1270.64 h60
  text "YES" at 12312.96,1270.64 h60
  text "REQUIRED" at 13174.46,1114.49 h60
  text "BARE BOARD ELEC. TEST:" at 11407.23,1111.64 h60
  text "NONE" at 12712.96,1111.64 h60
  text "X" at 13047.46,1111.64 h60
  text "PER ORDER" at 13766.46,1111.64 h60
  text "MANUFACTURER'S UL:" at 11407.23,954.64 h60
  text "RAIL" at 12572.96,950.35 h60
  text "METAL" at 13064.77,950.35 h60
  text "X" at 13440,950 h60
  text "SILK" at 13576.46,950.35 h60
  text ".Layer_Name" at 577,-858.49 h60
M11 Gerber Information:
  lines w10: -292,-930.17 6308,-930.17 ; -292,-726.83 6310,-726.83 ; -292,-523.5 -292,-1133.5 3713,-1133.5 6310,-1133.5 6310,-523.5 -291.5,-523.5 -291.5,-1133.5 1284,-1133.5 ; 2173,-1133.5 2173,-523.5 ; 3440,-726.83 3440,-523.5 ; 4280,-726.83 4280,-523.5 ; 4902,-1140 4902,-937.17
  text "ALL ARTWORK VIEWED FROM TOP SIDE" at -228.5,-655.67 h60
  text "BOARD #:" at 2248,-655.67 h60
  text ".PRJ_Number" at 2793.5,-655.67 h60
  text "REV:" at 3638,-655.67 h60
  text ".PCB_Rev" at 3929.5,-655.67 h60
  text "SVN REV:" at 4476,-655.67 h60
  text ".VersionControl_RevNumber" at 4982,-655.67 h60
  text "LAYER NAME =" at -228.5,-858.49 h60
  text "PLOT NAME =" at -228.5,-1064.34 h60
  text ".plot_File_Name" at 577,-1064.34 h60
  text "GENERATED    :" at 2250,-1064.34 h60
  text ".Print_Date" at 3119.5,-1064.34 h60
  text ".Print_Time" at 3848.5,-1064.34 h60
  text "TEXAS INSTRUMENTS" at 5113,-1064.34 h60
M12 Stackup:
  drawing of 191 lines, arcs and shapes, not listed
  text "Layer" at 9315,7835 h60
  text "Name" at 9724.91,7835 h60
  text "Material" at 11134.5,7835 h60
  text "Thickness" at 11994.27,7835 h60
  text "Constant" at 12644.1,7835 h60
  text "Board Layer Stack" at 13213.97,7835 h60
  text "1" at 9315,7715 h60
  text "Top Overlay" at 9724.91,7715 h60
  text "2" at 9315,7595 h60
  text "Top Solder" at 9724.91,7595 h60
  text "Solder Resist" at 11134.5,7595 h60
  text "0.40mil" at 11994.27,7595 h60
  text "3.5" at 12644.1,7595 h60
  text "3" at 9315,7475 h60
  text "Layer 1 - Top Layer" at 9724.91,7475 h60
  text "Copper" at 11134.5,7475 h60
  text "1.40mil" at 11994.27,7475 h60
  text "4" at 9315,7355 h60
  text "Dielectric1" at 9724.91,7355 h60
  text "370HR" at 11134.5,7355 h60
  text "90.20mil" at 11994.27,7355 h60
  text "4.8" at 12644.1,7355 h60
  text "5" at 9315,7235 h60
  text "Layer 2 - Bottom Layer" at 9724.91,7235 h60
  text "Copper" at 11134.5,7235 h60
  text "1.40mil" at 11994.27,7235 h60
  text "6" at 9315,7115 h60
  text "Bottom Solder" at 9724.91,7115 h60
  text "Solder Resist" at 11134.5,7115 h60
  text "0.40mil" at 11994.27,7115 h60
  text "3.5" at 12644.1,7115 h60
  text "7" at 9315,6995 h60
  text "Bottom Overlay" at 9724.91,6995 h60
  text ".Layer_Name" at 577,-858.49 h60
M13 Component Bodies Top:
  text ".Layer_Name" at 577,-858.49 h60
M14 Component Bodies Bottom:
  text ".Layer_Name" at 577,-858.49 h60
M15 Courtyards Top:
  text ".Layer_Name" at 577,-858.49 h60
M16 Courtyards Bottom:
  text ".Layer_Name" at 577,-858.49 h60
Drill Drawing:
  circle w1: c5592.72,1972.4 r24.89
  lines w1: 5567.83,1362.68 5580.27,1362.68 5580.27,1350.24 5605.16,1350.24 5605.16,1362.68 5617.6,1362.68 5617.6,1387.57 5605.16,1387.57 5605.16,1400.01 5580.27,1400.01 5580.27,1387.57 5567.83,1387.57 5567.83,1362.68 ; 5567.83,1499.56 5592.72,1512 5617.6,1499.56 5605.16,1524.44 5617.6,1549.33 5592.72,1536.89 5567.83,1549.33 5580.27,1524.44 5567.83,1499.56 ; 5567.83,1661.32 5580.27,1661.32 5592.72,1648.88 5605.16,1661.32 5617.6,1661.32 5605.16,1673.76 5617.6,1686.21 5605.16,1686.21 5592.72,1698.65 5580.27,1686.21 5567.83,1686.21 5580.27,1673.76 5567.83,1661.32 ; 5567.83,1847.97 5617.6,1847.97 5592.72,1798.2 5567.83,1847.97 ; 5567.83,2121.72 5592.72,2096.84 5617.6,2121.72 5592.72,2146.61 5567.83,2121.72 ; 5567.83,2246.16 5617.6,2246.16 5617.6,2295.93 5567.83,2295.93 5567.83,2246.16
  lines w12: 5500,1305.44 7618.02,1305.44 ; 5500,2350.68 7618.02,2350.68 ; 5870.36,1156.12 5870.36,2500 ; 6227.36,1156.12 6227.36,2500 ; 6888.93,1156.12 6888.93,2500 ; 7173.07,1156.12 7173.07,2500 ; 5500,1156.12 7618.02,1156.12 7618.02,2500 5500,2500 5500,1156.12
  text "Symbol" at 5589.59,2395.48 h72
  text "Quantity" at 5915.16,2395.48 h72
  text "Finished Hole Size" at 6272.16,2395.48 h72
  text "Plated" at 6933.72,2395.48 h72
  text "Hole Type" at 7217.86,2395.48 h72
  text "1" at 5915.16,2246.16 h60
  text "185.00mil (4.699mm)" at 6272.16,2246.16 h60
  text "NPTH" at 6933.72,2246.16 h60
  text "Round" at 7217.86,2246.16 h60
  text "58" at 5915.16,2096.84 h60
  text "12.00mil (0.305mm)" at 6272.16,2096.84 h60
  text "PTH" at 6933.72,2096.84 h60
  text "Round" at 7217.86,2096.84 h60
  text "6" at 5915.16,1947.52 h60
  text "26.00mil (0.660mm)" at 6272.16,1947.52 h60
  text "PTH" at 6933.72,1947.52 h60
  text "Round" at 7217.86,1947.52 h60
  text "30" at 5915.16,1798.2 h60
  text "33.46mil (0.850mm)" at 6272.16,1798.2 h60
  text "PTH" at 6933.72,1798.2 h60
  text "Round" at 7217.86,1798.2 h60
  text "2" at 5915.16,1648.88 h60
  text "50.00mil (1.270mm)" at 6272.16,1648.88 h60
  text "PTH" at 6933.72,1648.88 h60
  text "Round" at 7217.86,1648.88 h60
  text "3" at 5915.16,1499.56 h60
  text "72.83mil (1.850mm)" at 6272.16,1499.56 h60
  text "PTH" at 6933.72,1499.56 h60
  text "Round" at 7217.86,1499.56 h60
  text "4" at 5915.16,1350.24 h60
  text "125.98mil (3.200mm)" at 6272.16,1350.24 h60
  text "PTH" at 6933.72,1350.24 h60
  text "Round" at 7217.86,1350.24 h60
  text "104 Total" at 5915.16,1200.92 h60
  text ".Layer_Name" at 577,-858.49 h60

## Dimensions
0,0 to 0,2500 on M2 Board Dimensions
0,0 to 5000,0 on M2 Board Dimensions
0,-400 to 1000,-400 on M2 Board Dimensions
